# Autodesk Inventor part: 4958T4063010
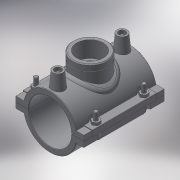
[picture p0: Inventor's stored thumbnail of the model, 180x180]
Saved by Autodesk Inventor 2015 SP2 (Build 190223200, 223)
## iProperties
Created: 2017-07
Part Number: 4958T4063010
Material: Generic
Description: PLASSON SADDLE 63X1" FEMALE BSPP
Document SubType Name: Modeling
Designer: KIM
Density: 1 g/cm^3
Appearance: Default
Author: KIM
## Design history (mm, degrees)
derived "4958T4.ipt"
feature "Solid1::4958T4.ipt"
tag "TaggingFeature1"
body "Solid1"
other parameters: "d0" = 63, "d1" = 78.75, "d3" = 15.75, "d4" = 118, "d5" = 0, "d6" = 0.1, "d8" = 0, "d19" = 6, "d20" = 6, "d21" = 70.8, "d23" = 0, "d24" = 35.4, "d26" = 0, "d27" = 3, "d28" = 3, "d29" = 3, "d30" = 24.00694, "d31" = 6, "d32" = 0, "d33" = 0, "d34" = 0.6, "d40" = 42.21, "d41" = 63, "d43" = 0, "d45" = 0, "d46" = 6.3, "d47" = 61.5, "d48" = 39.3783, "d50" = 0, "d51" = 30.291, "d52" = 24, "d53" = 0, "d54" = 24.2328, "d56" = 0, "d57" = -9, "d58" = 0.5, "d59" = 0.1, "d60" = 0, "d61" = 0.5, "d64" = 0.90873, "d67" = 0.63, "d70" = 15, "d72" = 0, "d73" = 6, "d75" = 5, "d76" = 0, "d77" = 3.15, "d78" = 60.5, "d79" = 15, "d80" = 47.2, "d82" = 5 deg, "d84" = 4, "d85" = 14, "d86" = 0, "d87" = 3, "d88" = 0, "d89" = 1, "d90" = 1, "d91" = 94.4, "d92" = 0, "d93" = 0.5, "d94" = 33.15789, "d_" = 63, "Rp_" = 30.291, "L_" = 118, "d_t" = 6
